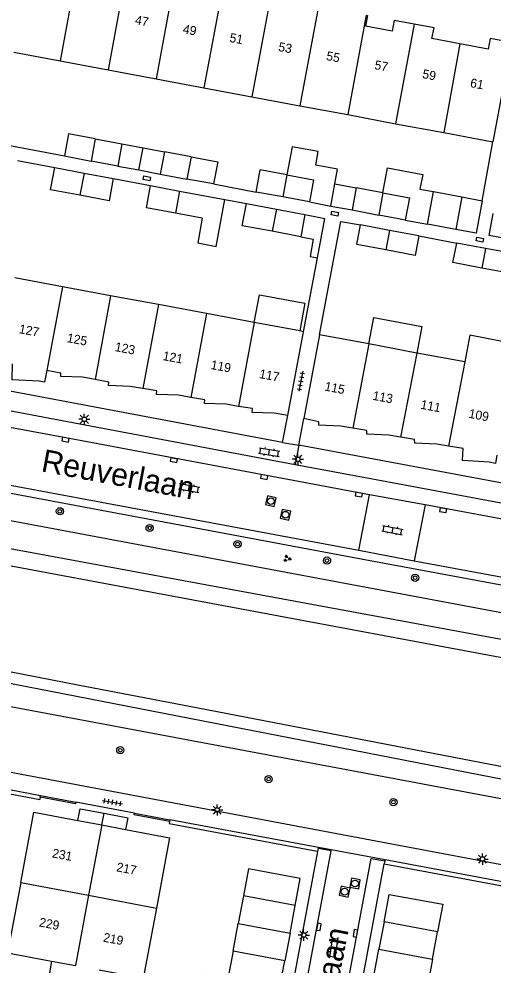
# Model space of a CAD drawing. Extents: x 124000 to 128010, y 398999 to 403000.
# Drawn here: x 126583.8 to 126636.3, y 399560.1 to 399664.9 of the extents above; entities that cross this region are included whole.
import ezdxf

# ---------------------------------------------------------------- set-up
doc = ezdxf.new("R2010")
doc.units = 0
for name, color, linetype in [('gg-afsc-erfafscheiding', 7, 'Continuous'), ('gg-afsc-hekwerk', 7, 'Continuous'), ('gg-afsc-muur', 7, 'Continuous'), ('gg-anno-huisnummerreeks BGT', 7, 'Continuous'), ('gg-anno-openbare ruimte label', 7, 'Continuous'), ('gg-bbg-bijgebouw', 7, 'Continuous'), ('gg-bbg-gedigitaliseerde bebouwing', 7, 'Continuous'), ('gg-bbg-gedigitaliseerde bijgebouw', 7, 'Continuous'), ('gg-bbg-hoofdgebouw', 7, 'Continuous'), ('gg-bbg-luifel en loopbrug', 7, 'Continuous'), ('gg-bbg-tussenscheiding', 7, 'Continuous'), ('gg-knt-BGT kruinlijn', 7, 'Continuous'), ('gg-knt-verharding', 7, 'Continuous'), ('gg-knt-verharding nz', 7, 'Continuous'), ('gg-kntw-beschoeiing', 7, 'Continuous'), ('gt-grn-groengrens', 7, 'Continuous'), ('gt-grn-weggrens', 7, 'Continuous'), ('gt-symb-boom', 7, 'Continuous'), ('gt-symb-groenvak', 7, 'Continuous'), ('gt-symb-klinker verharding', 7, 'Continuous'), ('gt-symb-kolk', 7, 'Continuous'), ('gt-symb-kolk center center', 7, 'Continuous'), ('gt-symb-lichtmast', 7, 'Continuous'), ('gt-symb-rioolschacht', 7, 'Continuous'), ('gt-symb-tegel verharding', 7, 'Continuous')]:
    doc.layers.add(name, color=color, linetype=linetype)

# ---------------------------------------------------------------- blocks, each defined once
blk = doc.blocks.new('gt0-KOLKCC')
at = {"layer": 'gt-symb-kolk center center'}
blk.add_lwpolyline([(-0.38, 0.2), (0.37, 0.2), (0.37, -0.2), (-0.38, -0.2)], close=True, dxfattribs=at)
blk = doc.blocks.new('gt0-LMAST')
at = {"layer": 'gt-symb-lichtmast'}
for p, q in [((-0.18, 0.17), (-0.45, 0.44)), ((-0.01, 0.25), (-0.01, 0.62)), ((0.17, 0.17), (0.44, 0.44)), ((-0.26, 0), (-0.63, 0)), ((-0.18, -0.18), (-0.45, -0.45)), ((-0.01, -0.25), (-0.01, -0.63)), ((0.44, -0.45), (0.17, -0.18)), ((0.24, 0), (0.62, 0))]:
    blk.add_line(p, q, dxfattribs=at)
blk.add_circle((-0.01, 0), 0.25, dxfattribs=at)
blk = doc.blocks.new('gt0-TEG1')
at = {"layer": 'gt-symb-tegel verharding'}
for p, q in [((-1.12, 0), (1.12, 0)), ((-0.9, -0.25), (-0.9, 0.25)), ((-0.45, -0.25), (-0.45, 0.25)), ((0, -0.25), (0, 0.25)), ((0.45, -0.25), (0.45, 0.25)), ((0.9, -0.25), (0.9, 0.25))]:
    blk.add_line(p, q, dxfattribs=at)
blk = doc.blocks.new('gt0-KOLK')
at = {"layer": 'gt-symb-kolk'}
blk.add_lwpolyline([(0, 0), (0.38, 0), (0.38, 0.4), (-0.38, 0.4), (-0.38, 0), (0, 0)], dxfattribs=at)
blk = doc.blocks.new('gt0-KL1')
at = {"layer": 'gt-symb-klinker verharding'}
for p, q in [((-1.15, 0.3), (1.15, 0.3)), ((-1, -0.3), (-1, 0.3)), ((-0.5, 0.3), (-0.5, 0.45)), ((0, -0.3), (0, 0.3)), ((0.5, 0.3), (0.5, 0.45)), ((1, -0.3), (1, 0.3)), ((-1.15, -0.3), (1.15, -0.3)), ((-0.5, -0.45), (-0.5, -0.3)), ((0.5, -0.45), (0.5, -0.3))]:
    blk.add_line(p, q, dxfattribs=at)
blk = doc.blocks.new('gt0-BOOM')
at = {"layer": 'gt-symb-boom'}
for radius in [0.4, 0.2]:
    blk.add_circle((0, 0), radius, dxfattribs=at)
blk = doc.blocks.new('gt0-GRVAK')
at = {"layer": 'gt-symb-groenvak'}
for p, q in [((-0.11, 0.19), (-0.23, 0.24)), ((-0.18, 0.15), (0.09, 0.15)), ((-0.09, 0.21), (-0.16, 0.32)), ((-0.05, 0.21), (-0.05, 0.39)), ((0, 0.21), (0.06, 0.32)), ((0.01, 0.19), (0.13, 0.24)), ((0.26, -0.05), (0.2, 0.06)), ((0.3, -0.05), (0.3, 0.13)), ((0.35, -0.05), (0.41, 0.06)), ((-0.25, -0.23), (-0.36, -0.18)), ((-0.32, -0.26), (-0.05, -0.26)), ((-0.23, -0.21), (-0.29, -0.1)), ((-0.18, -0.2), (-0.18, -0.02)), ((-0.14, -0.21), (-0.07, -0.1)), ((-0.12, -0.23), (0, -0.18)), ((0.24, -0.07), (0.12, -0.02)), ((0.17, -0.11), (0.44, -0.11)), ((0.37, -0.07), (0.49, -0.02))]:
    blk.add_line(p, q, dxfattribs=at)
blk = doc.blocks.new('gt0-RS')
at = {"layer": 'gt-symb-rioolschacht'}
blk.add_lwpolyline([(-0.5, -0.5), (0.5, -0.5), (0.5, 0.5), (-0.5, 0.5)], close=True, dxfattribs=at)
blk.add_circle((0, 0), 0.375, dxfattribs=at)

msp = doc.modelspace()

# ---------------------------------------------------------------- linework, layer by layer
at = {"layer": 'gg-afsc-erfafscheiding'}
for p, q in [((126580.33, 399651.36), (126588.81, 399649.74)), ((126583.6, 399649.23), (126587.73, 399648.45)), ((126594.22, 399647.23), (126598.34, 399646.46)), ((126605.33, 399646.64), (126610.05, 399645.75)), ((126606.58, 399644.91), (126608.96, 399644.47)), ((126617.07, 399629.94), (126619.43, 399642.5)), ((126619.43, 399642.5), (126621.62, 399642.1)), ((126628.07, 399640.89), (126632.26, 399640.1))]:
    msp.add_line(p, q, dxfattribs=at)
at = {"layer": 'gg-afsc-hekwerk'}
for p, q in [((126569.71, 399581.55), (126586.08, 399578.47)), ((126600.42, 399575.81), (126616.79, 399572.73)), ((126624.24, 399571.35), (126640.61, 399568.28))]:
    msp.add_line(p, q, dxfattribs=at)
at = {"layer": 'gg-afsc-muur'}
for p, q in [((126635.08, 399644.79), (126636.28, 399651.3)), ((126615.31, 399630.27), (126616.85, 399638.47)), ((126586.13, 399578.72), (126586.16, 399578.9)), ((126586.16, 399578.9), (126590.09, 399578.19)), ((126596.58, 399576.96), (126600.49, 399576.22)), ((126600.49, 399576.22), (126600.46, 399576.05))]:
    msp.add_line(p, q, dxfattribs=at)
for points in [[(126590.09, 399578.19), (126590.05, 399577.99), (126586.13, 399578.72)], [(126600.46, 399576.05), (126596.54, 399576.79), (126596.58, 399576.96)]]:
    msp.add_lwpolyline(points, dxfattribs=at)
at = {"layer": 'gg-bbg-bijgebouw'}
for p, q in [((126587.73, 399648.45), (126590.98, 399647.84)), ((126590.98, 399647.84), (126594.22, 399647.23)), ((126598.34, 399646.46), (126601.56, 399645.85)), ((126608.96, 399644.47), (126612.29, 399643.84)), ((126612.29, 399643.84), (126615.45, 399643.25)), ((126624.81, 399641.5), (126621.62, 399642.1)), ((126628.07, 399640.89), (126624.81, 399641.5)), ((126635.44, 399639.5), (126632.26, 399640.1)), ((126638.69, 399638.89), (126635.44, 399639.5)), ((126608.63, 399567.8), (126608.06, 399564.74)), ((126614.37, 399566.73), (126608.63, 399567.8)), ((126613.8, 399563.67), (126614.37, 399566.73)), ((126624.21, 399564.93), (126623.65, 399561.91)), ((126630.15, 399563.82), (126624.21, 399564.93)), ((126607.49, 399561.68), (126608.06, 399564.74)), ((126629.59, 399560.8), (126630.15, 399563.82)), ((126613.8, 399563.67), (126613.23, 399560.61)), ((126613.23, 399560.61), (126607.49, 399561.68)), ((126623.09, 399558.9), (126623.65, 399561.91)), ((126629.59, 399560.8), (126629.03, 399557.79))]:
    msp.add_line(p, q, dxfattribs=at)
at = {"layer": 'gg-bbg-gedigitaliseerde bebouwing'}
for p, q in [((126622.53, 399628.92), (126617.07, 399629.94)), ((126627.84, 399627.92), (126622.53, 399628.92)), ((126633.15, 399626.93), (126627.84, 399627.92))]:
    msp.add_line(p, q, dxfattribs=at)
msp.add_lwpolyline([(126638.46, 399625.93), (126639.01, 399628.88), (126633.7, 399629.88), (126633.15, 399626.93)], dxfattribs=at)
at = {"layer": 'gg-bbg-gedigitaliseerde bijgebouw'}
for p, q in [((126592.22, 399651.64), (126595.17, 399651.09)), ((126595.17, 399651.09), (126594.71, 399648.63)), ((126588.81, 399649.74), (126591.76, 399649.18)), ((126599.89, 399650.2), (126599.43, 399647.74)), ((126602.84, 399649.65), (126599.89, 399650.2)), ((126594.71, 399648.63), (126591.76, 399649.18)), ((126602.84, 399649.65), (126605.79, 399649.1)), ((126605.79, 399649.1), (126605.33, 399646.64)), ((126599.43, 399647.74), (126602.38, 399647.19)), ((126610.05, 399645.75), (126610.51, 399648.21)), ((126613.46, 399647.66), (126610.51, 399648.21)), ((126613.46, 399647.66), (126616.4, 399647.1)), ((126605.33, 399646.64), (126602.38, 399647.19)), ((126616.4, 399647.1), (126615.95, 399644.65)), ((126601.56, 399645.85), (126606.58, 399644.91)), ((126613, 399645.2), (126610.05, 399645.75)), ((126621.13, 399646.22), (126620.67, 399643.76)), ((126624.08, 399645.67), (126621.13, 399646.22)), ((126629.01, 399642.19), (126629.69, 399645.8)), ((126629.69, 399645.8), (126632.82, 399645.21)), ((126615.95, 399644.65), (126613, 399645.2)), ((126632.82, 399645.21), (126632.15, 399641.6)), ((126604.08, 399642.85), (126601.11, 399643.41)), ((126620.67, 399643.76), (126623.62, 399643.2)), ((126615.45, 399643.25), (126614.99, 399640.8)), ((126625.83, 399642.79), (126623.62, 399643.2)), ((126626.57, 399642.65), (126625.83, 399642.79)), ((126614.99, 399640.8), (126611.82, 399641.4)), ((126632.15, 399641.6), (126629.01, 399642.19))]:
    msp.add_line(p, q, dxfattribs=at)
for points in [[(126592.22, 399651.64), (126589.27, 399652.19), (126588.81, 399649.74)], [(126590.51, 399645.39), (126587.27, 399646), (126587.73, 399648.45)], [(126594.22, 399647.23), (126593.76, 399644.78), (126590.51, 399645.39)], [(126601.11, 399643.41), (126597.89, 399644.01), (126598.34, 399646.46)], [(126624.08, 399645.67), (126627.03, 399645.11), (126626.57, 399642.65)], [(126604.08, 399642.85), (126603.57, 399640.11), (126605.61, 399639.73), (126606.58, 399644.91)], [(126611.82, 399641.4), (126608.5, 399642.02), (126608.96, 399644.47)], [(126638.76, 399640.37), (126635.85, 399640.92), (126636.31, 399643.36)], [(126624.42, 399639.34), (126621.21, 399639.94), (126621.62, 399642.1)], [(126628.07, 399640.89), (126627.66, 399638.72), (126624.42, 399639.34)], [(126635.05, 399637.33), (126631.85, 399637.94), (126632.26, 399640.1)], [(126638.69, 399638.89), (126638.28, 399636.73), (126635.05, 399637.33)]]:
    msp.add_lwpolyline(points, dxfattribs=at)
at = {"layer": 'gg-bbg-hoofdgebouw'}
for p, q in [((126638.34, 399662.3), (126636.28, 399651.3)), ((126583.19, 399661.25), (126588.33, 399660.29)), ((126588.33, 399660.29), (126593.65, 399659.29)), ((126593.65, 399659.29), (126598.96, 399658.3)), ((126598.96, 399658.3), (126604.27, 399657.3)), ((126604.27, 399657.3), (126609.56, 399656.31)), ((126609.56, 399656.31), (126614.88, 399655.31)), ((126614.88, 399655.31), (126620.2, 399654.32)), ((126620.2, 399654.32), (126625.5, 399653.32)), ((126625.5, 399653.32), (126630.82, 399652.33)), ((126630.82, 399652.33), (126636.28, 399651.3)), ((126588.61, 399635.26), (126583.3, 399636.25)), ((126593.92, 399634.27), (126588.61, 399635.26)), ((126599.23, 399633.28), (126593.92, 399634.27)), ((126604.53, 399632.29), (126599.23, 399633.28)), ((126609.84, 399631.3), (126604.53, 399632.29)), ((126614.88, 399630.36), (126609.84, 399631.3)), ((126613.57, 399621), (126615.31, 399630.27)), ((126615.31, 399630.27), (126614.88, 399630.36)), ((126617.07, 399629.94), (126615.32, 399620.66)), ((126632.96, 399617.33), (126631.36, 399617.61)), ((126590.31, 399576.15), (126592.95, 399575.65)), ((126592.95, 399575.65), (126595.59, 399575.16)), ((126587.39, 399560.56), (126590.02, 399560.07))]:
    msp.add_line(p, q, dxfattribs=at)
for points in [[(126622.24, 399665.33), (126622.39, 399665.31), (126622.17, 399664.13)], [(126627.55, 399664.34), (126625.35, 399664.75), (126625.12, 399663.57), (126622.17, 399664.13)], [(126632.62, 399662.16), (126629.52, 399662.74), (126629.75, 399663.92), (126627.55, 399664.34)], [(126638.34, 399662.3), (126635.95, 399662.76), (126635.73, 399661.58), (126632.62, 399662.16)], [(126586.87, 399625.98), (126586.62, 399624.68), (126586, 399624.8), (126583.01, 399624.96), (126583.05, 399626.71)], [(126592.2, 399624.99), (126590.83, 399625.24), (126588.4, 399625.32), (126588.42, 399625.69), (126586.87, 399625.98)], [(126597.48, 399623.99), (126596.11, 399624.22), (126593.7, 399624.32), (126593.74, 399624.7), (126592.2, 399624.99)], [(126602.81, 399623), (126601.43, 399623.24), (126599.01, 399623.33), (126599.03, 399623.73), (126597.48, 399623.99)], [(126608.11, 399622.01), (126606.73, 399622.24), (126604.31, 399622.34), (126604.36, 399622.73), (126602.81, 399623)], [(126613.57, 399621), (126612.03, 399621.25), (126609.61, 399621.34), (126609.66, 399621.76), (126608.11, 399622.01)], [(126620.75, 399619.59), (126619.44, 399619.81), (126617, 399619.94), (126616.98, 399620.3), (126615.32, 399620.66)], [(126626.05, 399618.6), (126624.75, 399618.83), (126622.32, 399618.95), (126622.29, 399619.32), (126620.75, 399619.59)], [(126631.36, 399617.61), (126630.06, 399617.84), (126627.62, 399617.95), (126627.6, 399618.33), (126626.05, 399618.6)], [(126636.71, 399616.61), (126636.55, 399615.67), (126635.84, 399615.82), (126632.9, 399616), (126632.96, 399617.33)], [(126583.98, 399569.27), (126585.44, 399577.06), (126590.31, 399576.15)], [(126595.59, 399575.16), (126600.46, 399574.24), (126599, 399566.45)], [(126583.98, 399569.27), (126582.52, 399561.47), (126587.39, 399560.56)], [(126599, 399566.45), (126597.53, 399558.66), (126592.66, 399559.57)]]:
    msp.add_lwpolyline(points, dxfattribs=at)
at = {"layer": 'gg-bbg-luifel en loopbrug'}
for p, q in [((126595.17, 399651.09), (126597.53, 399650.65)), ((126597.07, 399648.19), (126597.53, 399650.65)), ((126597.53, 399650.65), (126599.89, 399650.2)), ((126594.71, 399648.63), (126597.07, 399648.19)), ((126597.07, 399648.19), (126599.43, 399647.74)), ((126618.31, 399644.2), (126618.77, 399646.66)), ((126618.77, 399646.66), (126621.13, 399646.22)), ((126615.95, 399644.65), (126618.31, 399644.2)), ((126632.82, 399645.21), (126635.08, 399644.79)), ((126618.31, 399644.2), (126620.67, 399643.76)), ((126615.45, 399643.25), (126617.67, 399642.83)), ((126616.85, 399638.47), (126617.67, 399642.83)), ((126626.57, 399642.65), (126629.01, 399642.19)), ((126592.95, 399575.65), (126593.2, 399576.94))]:
    msp.add_line(p, q, dxfattribs=at)
for points in [[(126618.77, 399646.66), (126619.07, 399648.27), (126616.65, 399648.72), (126616.93, 399650.23), (126614.04, 399650.77), (126613.46, 399647.66)], [(126624.08, 399645.67), (126624.6, 399648.43), (126628.5, 399647.69), (126628.19, 399646.08), (126629.69, 399645.8)], [(126635.08, 399644.79), (126634.41, 399641.18), (126632.15, 399641.6)], [(126614.99, 399640.8), (126616.38, 399640.54), (126616.02, 399638.62), (126616.85, 399638.47)], [(126609.84, 399631.3), (126610.42, 399634.38), (126615.45, 399633.43), (126614.88, 399630.36)], [(126622.53, 399628.92), (126623.09, 399631.85), (126628.39, 399630.86), (126627.84, 399627.92)], [(126590.31, 399576.15), (126590.56, 399577.44), (126593.2, 399576.94)], [(126593.2, 399576.94), (126595.83, 399576.43), (126595.59, 399575.16)], [(126614.37, 399566.73), (126614.92, 399569.72), (126609.19, 399570.79), (126608.63, 399567.8)], [(126624.21, 399564.93), (126624.79, 399567.96), (126630.72, 399566.86), (126630.15, 399563.82)], [(126607.49, 399561.68), (126606.92, 399558.64), (126603.97, 399559.2), (126603.36, 399555.94), (126608.27, 399555.03), (126608.88, 399558.28), (126612.65, 399557.57), (126613.23, 399560.61)], [(126587.39, 399560.56), (126587.14, 399559.28), (126589.78, 399558.78)]]:
    msp.add_lwpolyline(points, dxfattribs=at)
at = {"layer": 'gg-bbg-tussenscheiding'}
for p, q in [((126590.17, 399670.1), (126588.33, 399660.29)), ((126595.7, 399670.3), (126593.65, 399659.29)), ((126600.8, 399668.13), (126598.96, 399658.3)), ((126606.33, 399668.32), (126604.27, 399657.3)), ((126611.41, 399666.15), (126609.56, 399656.31)), ((126616.94, 399666.33), (126614.88, 399655.31)), ((126622.24, 399665.33), (126620.2, 399654.32)), ((126627.55, 399664.34), (126625.5, 399653.32)), ((126632.62, 399662.16), (126630.82, 399652.33)), ((126592.22, 399651.64), (126591.76, 399649.18)), ((126602.84, 399649.65), (126602.38, 399647.19)), ((126590.98, 399647.84), (126590.51, 399645.39)), ((126613.46, 399647.66), (126613, 399645.2)), ((126601.56, 399645.85), (126601.11, 399643.41)), ((126624.08, 399645.67), (126623.62, 399643.2)), ((126612.29, 399643.84), (126611.82, 399641.4)), ((126624.81, 399641.5), (126624.42, 399639.34)), ((126635.44, 399639.5), (126635.05, 399637.33)), ((126588.61, 399635.26), (126586.87, 399625.98)), ((126593.92, 399634.27), (126592.2, 399624.99)), ((126599.23, 399633.28), (126597.48, 399623.99)), ((126604.53, 399632.29), (126602.81, 399623)), ((126609.84, 399631.3), (126608.11, 399622.01)), ((126622.53, 399628.92), (126620.75, 399619.59)), ((126627.84, 399627.92), (126626.05, 399618.6)), ((126633.15, 399626.93), (126631.36, 399617.61)), ((126592.95, 399575.65), (126591.49, 399567.86)), ((126583.98, 399569.27), (126591.49, 399567.86)), ((126591.49, 399567.86), (126590.02, 399560.07)), ((126591.49, 399567.86), (126599, 399566.45)), ((126608.06, 399564.74), (126613.8, 399563.67)), ((126623.65, 399561.91), (126629.59, 399560.8))]:
    msp.add_line(p, q, dxfattribs=at)
at = {"layer": 'gg-knt-BGT kruinlijn'}
for points in [[(126531.95, 399618.88), (126672.48, 399592.59), (126676.06, 399590.91), (126677.97, 399589.61), (126679.53, 399589.32)], [(126532.02, 399598.31), (126670.06, 399572.43), (126673.39, 399572.63), (126676.36, 399572.6)]]:
    msp.add_lwpolyline(points, dxfattribs=at)
at = {"layer": 'gg-knt-verharding'}
for p, q in [((126612.98, 399618.02), (126551.03, 399629.63)), ((126612.98, 399618.02), (126613.57, 399621)), ((126614.77, 399617.73), (126615.32, 399620.66)), ((126612.98, 399618.02), (126614.77, 399617.73)), ((126676.82, 399606.09), (126614.77, 399617.73)), ((126574.38, 399614.85), (126621.41, 399606.08)), ((126621.41, 399606.08), (126622.6, 399612.22)), ((126628.76, 399611.09), (126627.56, 399604.89)), ((126621.41, 399606.08), (126627.56, 399604.89)), ((126569.71, 399582.09), (126586.16, 399578.9)), ((126596.58, 399576.96), (126590.09, 399578.19)), ((126616.96, 399573.14), (126600.49, 399576.22)), ((126616.88, 399572.71), (126616.94, 399573.05)), ((126616.94, 399573.05), (126616.96, 399573.14)), ((126624.33, 399571.79), (126616.96, 399573.14)), ((126624.3, 399571.68), (126624.24, 399571.35)), ((126624.33, 399571.79), (126624.3, 399571.68)), ((126640.69, 399568.73), (126624.33, 399571.79))]:
    msp.add_line(p, q, dxfattribs=at)
for points in [[(126553.93, 399625.5), (126554.14, 399626.5), (126554.3, 399626.72), (126554.56, 399626.8), (126575.84, 399622.83), (126614.37, 399615.59)], [(126523.93, 399623.43), (126621.67, 399605.12), (126668.04, 399596.54), (126675.39, 399595.75)], [(126614.37, 399615.59), (126622.94, 399613.98), (126666.87, 399605.8), (126671.81, 399605.02), (126672.05, 399604.86), (126672.14, 399604.59), (126672, 399603.56)], [(126627.56, 399604.89), (126670.29, 399596.99), (126675.46, 399596.56)], [(126674.98, 399564.69), (126674.78, 399564.46), (126674.44, 399564.36), (126672.56, 399564.59), (126511.62, 399594.85)], [(126604.78, 399500), (126618.35, 399572.78), (126616.94, 399573.05)], [(126613.86, 399554.12), (126613.88, 399554.21), (126613.44, 399554.31), (126616.88, 399572.71)], [(126609.33, 399500), (126622.8, 399571.94), (126624.3, 399571.68)], [(126620.26, 399552.88), (126620.29, 399553.03), (126620.78, 399552.94), (126624.24, 399571.35)]]:
    msp.add_lwpolyline(points, dxfattribs=at)
at = {"layer": 'gg-knt-verharding nz'}
for p, q in [((126628.76, 399611.09), (126622.6, 399612.22)), ((126672.29, 399603.07), (126628.76, 399611.09))]:
    msp.add_line(p, q, dxfattribs=at)
msp.add_lwpolyline([(126622.6, 399612.22), (126588.96, 399618.52), (126575.51, 399621)], dxfattribs=at)
at = {"layer": 'gg-kntw-beschoeiing'}
for p, q in [((126590.28, 399591.15), (126543.22, 399600.21)), ((126603.61, 399588.58), (126590.28, 399591.15))]:
    msp.add_line(p, q, dxfattribs=at)
for points in [[(126571.79, 399606.42), (126673.85, 399587.36), (126675.51, 399584.87), (126678.57, 399584.27)], [(126677.3, 399577.57), (126674.27, 399578.08), (126671.62, 399576.61), (126668.64, 399577.17), (126667.27, 399576.82), (126663.15, 399577.12), (126603.61, 399588.58)]]:
    msp.add_lwpolyline(points, dxfattribs=at)
at = {"layer": 'gt-grn-groengrens'}
for p, q in [((126586.13, 399578.72), (126586.08, 399578.47)), ((126600.46, 399576.05), (126600.42, 399575.81)), ((126616.79, 399572.73), (126616.88, 399572.71))]:
    msp.add_line(p, q, dxfattribs=at)
for points in [[(126525.23, 399611.9), (126526.33, 399614.46), (126528.75, 399616.22), (126674.21, 399589.4), (126676.4, 399586.11), (126678.82, 399585.55)], [(126677.07, 399576.37), (126674.31, 399576.85), (126672.4, 399575.52), (126666.96, 399574.93), (126528.68, 399601.85), (126526.9, 399603.28), (126525.83, 399605.01), (126525.25, 399606.71), (126524.97, 399607.9)]]:
    msp.add_lwpolyline(points, dxfattribs=at)
at = {"layer": 'gt-grn-weggrens'}
msp.add_line((126614.77, 399617.73), (126614.37, 399615.59), dxfattribs=at)

# ---------------------------------------------------------------- block references
at = {"layer": 'gt-symb-boom'}
for p in [(126588.31, 399610.39), (126598.25, 399608.54), (126607.99, 399606.76), (126617.9, 399604.93), (126627.66, 399603.03), (126595, 399583.93), (126611.43, 399580.73), (126625.25, 399578.18)]:
    msp.add_blockref('gt0-BOOM', p, dxfattribs=at)
at = {"layer": 'gt-symb-groenvak'}
msp.add_blockref('gt0-GRVAK', (126613.47, 399605.16), dxfattribs=at)
at = {"layer": 'gt-symb-klinker verharding'}
for p, rotation in [((126611.49, 399616.93), -8.9726266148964), ((126602.62, 399612.97), -10.71464389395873), ((126625.16, 399608.31), -10.714643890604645), ((126618.62, 399562.08), -98.39757257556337)]:
    msp.add_blockref('gt0-KL1', p, dxfattribs=dict(at, rotation=rotation))
at = {"layer": 'gt-symb-kolk'}
for p, rotation in [((126588.96, 399618.52), 169.5106101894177), ((126600.96, 399616.25), 169.2853561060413), ((126610.98, 399614.39), 169.45426563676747), ((126621.47, 399612.44), 169.4542656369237), ((126630.81, 399610.71), 169.5669752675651), ((126616.8, 399564.39), -99.84862238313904), ((126621.24, 399563.61), 79.39794170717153)]:
    msp.add_blockref('gt0-KOLK', p, dxfattribs=dict(at, rotation=rotation))
at = {"layer": 'gt-symb-kolk center center'}
for p, rotation in [((126597.92, 399647.27), 169.34163849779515), ((126618.76, 399643.35), 169.34163849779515), ((126634.82, 399640.47), -10.545734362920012)]:
    msp.add_blockref('gt0-KOLKCC', p, dxfattribs=dict(at, rotation=rotation))
at = {"layer": 'gt-symb-lichtmast'}
for p in [(126591.02, 399620.58), (126614.68, 399616.15), (126605.73, 399577.31), (126635.12, 399571.88), (126615.32, 399563.46)]:
    msp.add_blockref('gt0-LMAST', p, dxfattribs=at)
at = {"layer": 'gt-symb-rioolschacht'}
for p, rotation in [((126611.67, 399611.51), 167.88123966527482), ((126613.3, 399610.01), -12.118760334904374), ((126621, 399569.17), 79.85920685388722), ((126619.85, 399568.26), 167.28466301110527)]:
    msp.add_blockref('gt0-RS', p, dxfattribs=dict(at, rotation=rotation))
at = {"layer": 'gt-symb-tegel verharding'}
for p, rotation in [((126615, 399624.8), -100.65836150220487), ((126594.13, 399578.17), -10.074332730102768)]:
    msp.add_blockref('gt0-TEG1', p, dxfattribs=dict(at, rotation=rotation))

# ---------------------------------------------------------------- texts
at = {"layer": 'gg-anno-huisnummerreeks BGT'}
for s, rotation, p in [('47', 349.4, (126596.57, 399664.35)), ('49', 349.3, (126601.87, 399663.35)), ('51', 349.3, (126607.04, 399662.39)), ('53', 349.3, (126612.45, 399661.38)), ('55', 349.4, (126617.76, 399660.37)), ('57', 349.4, (126623.1, 399659.37)), ('59', 349.3, (126628.4, 399658.38)), ('61', 349.3, (126633.69, 399657.38)), ('127', 349.4, (126583.72, 399630.13)), ('125', 349.5, (126589.03, 399629.14)), ('123', 349.3, (126594.34, 399628.15)), ('121', 349.5, (126599.64, 399627.15)), ('119', 349.5, (126604.96, 399626.16)), ('117', 349.5, (126610.33, 399625.16)), ('115', 348.9, (126617.57, 399623.78)), ('113', 349.4, (126622.89, 399622.75)), ('111', 349.4, (126628.2, 399621.76)), ('109', 349.4, (126633.53, 399620.76)), ('231', 349.4, (126587.39, 399572.07)), ('217', 349.3, (126594.51, 399570.53)), ('229', 349.3, (126585.95, 399564.42)), ('219', 349.4, (126593.04, 399562.74))]:
    msp.add_text(s, height=1, rotation=rotation, dxfattribs=at).set_placement(p)
at = {"layer": 'gg-anno-openbare ruimte label'}
for s, rotation, p in [('Reuverlaan', 349.4, (126586.14, 399614.83)), ('Schipluidenlaan', 78.8, (126615.72, 399540.86))]:
    msp.add_text(s, height=2.5, rotation=rotation, dxfattribs=at).set_placement(p)

doc.saveas('drawing.dxf')
